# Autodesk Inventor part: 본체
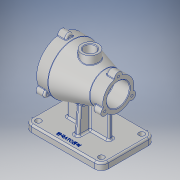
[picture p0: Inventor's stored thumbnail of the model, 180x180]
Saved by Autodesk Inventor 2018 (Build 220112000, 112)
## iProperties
Created: 2020-03
Part Number: 본체
Material: 알루미늄 6061
Document SubType Name: Modeling
Designer: USER
Density: 2.7 g/cm^3
Appearance: 알루미늄 - 평지
Mass: 1007.92 g
Surface Area: 869.539 cm^2
Volume: 373.303 cm^3
Author: USER
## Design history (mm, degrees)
sketch "스케치1"
  geometry: L1 (0, 0)-(100, 0); L2 (100, 0)-(100, 27.5); L3 (100, 27.5)-(77, 27.5); L4 (77, 27.5)-(20, 44); L5 (20, 44)-(0, 44); L6 (0, 44)-(0, 0); L7 (0, 0)-(107.225, 0)
  constraints: 14 end point, 3 perpendicular, 2 horizontal, 1 parallel
  dimensions: "d0" = 20 distance from line of L4.end L6; "d1" = 55 diameter of L3 L7; "d2" = 100 distance between parallel lines of L2 L6; "d3" = 77 distance from line of L3.end L6; "d4" = 88 diameter of L5 L7
revolve "회전1" sketch "스케치1" stored, may be unused: angle "d5" = 90 deg
sketch "스케치2"
  geometry: L1 (0, 0)-(23, 0); L2 (23, 0)-(23, 36); L3 (23, 36)-(0, 36); L4 (0, 36)-(0, 0); L5 (23, 0)-(70, 0); L6 (70, 0)-(70, 26); L7 (70, 26)-(23, 26); L8 (23, 26)-(23, 0); L9 (70, 0)-(100, 0); L10 (100, 0)-(100, 20); L11 (100, 20)-(70, 20); L12 (70, 20)-(70, 0); L13 (100, -27.5)-(100, 27.5) reference; L14 (0, 0)-(130.943, 0)
  constraints: 26 end point, 6 parallel, 4 horizontal, 3 perpendicular, 1 midpoint
  dimensions: "d6" = 40 diameter of L11 L14; "d7" = 52 diameter of L7 L14; "d8" = 72 diameter of L3 L14; "d9" = 23 distance between parallel lines of L2 L4; "d10" = 47 distance between parallel lines of L6 L2
revolve "회전2" sketch "스케치2" stored, may be unused: angle "d11" = 90 deg
node "작업 평면1"
sketch "스케치3"
  geometry: C1 r 15 at (-50, 0); 1 further point
  constraints: 1 centre point, 1 horizontal alignment
  dimensions: "d13" = 30 diameter of C1; "d14" = 50 distance of point (0, 0) C1.centre
extrude "돌출1" join sketch "스케치3" stored distance "d15" = 10; taper "d16" = 0 deg
sketch "스케치4"
  geometry: C1 r 15 at (0, 0) reference; C2 r 10 at (0, 0); 1 further point
  constraints: 1 centre point, 1 coincident
  dimensions: "d17" = 20 diameter of C2
extrude "돌출2" cut sketch "스케치4" distance "d18" = 25.75; taper "d19" = 0 deg
node "작업 평면2"
sketch "스케치6"
  geometry: L1 (0, 44)-(0, -44) reference; L2 (-100, 27.5)-(-100, -27.5) reference; L3 (17.5, -47.5)-(-117.5, -47.5); L4 (-117.5, -47.5)-(-117.5, 47.5); L5 (-117.5, 47.5)-(17.5, 47.5); L6 (17.5, 47.5)-(17.5, -47.5); L7 (0, 0)-(-100, 0); L8 (-50, 0)-(-50, -25.303)
  constraints: 12 end point, 2 midpoint, 2 parallel, 1 horizontal, 1 perpendicular, 1 vertical, 1 other
  dimensions: "d21" = 135 distance between parallel lines of L4 L6; "d22" = 95 distance between parallel lines of L5 L3; "d23" = 47.5 distance from line of L7.start L3
extrude "돌출3" join sketch "스케치6" distance "d24" = 12; taper "d25" = 0 deg
fillet "모깎기1" dims "d26" = 12
sketch "스케치7"
  geometry: L1 (13, 4)-(87, 4); L2 (87, 4)-(87, -4); L3 (87, -4)-(13, -4); L4 (13, -4)-(13, 4); L5 (117.5, 35.5)-(117.5, -35.5) reference; L6 (-17.5, -35.5)-(-17.5, 35.5) reference; L7 (-17.5, 0)-(117.5, 0); L8 (50, 0)-(50, 35.5); 1 further point
  constraints: 12 end point, 3 midpoint, 2 parallel, 1 horizontal, 1 perpendicular, 1 vertical, 1 other
  dimensions: "d27" = 74 distance between parallel lines of L2 L4; "d28" = 8 distance between parallel lines of L3 L1; "d29" = 4 distance from line of point (0, 0) L1
extrude "돌출4" join sketch "스케치7" stored distance "d30" = 12; taper "d31" = 0 deg
node "작업 평면3"
sketch "스케치8"
  geometry: L1 (39.5, 12)-(39.5, 43.182) reference; L2 (31.5, 12)-(39.5, 12) reference; L3 (31.5, 12)-(31.5, 43.182) reference; L4 (31.5, 12)-(39.5, 12) reference; L5 (10.5, 12)-(31.5, 12); L6 (71, 12)-(0, 12) reference; L7 (10.5, 12)-(14.999, 63.425); L8 (14.999, 63.425)-(31.5, 53.896); L9 (31.5, 53.896)-(31.5, 12); L10 (-12, 12)-(0, 12) reference; L11 (35.5, 43)-(35.5, 12); C1 r 36 at (35.5, 87) reference; C2 r 36 at (35.5, 87) reference; C3 r 44 at (35.5, 87) reference; A1 r 44 centre (35.5, 87) between (31.5, 43.182) and (39.5, 43.182) reference; A2 r 44 centre (35.5, 87) between (31.5, 43.182) and (39.5, 43.182) reference; 1 further point
  constraints: 10 end point, 2 point on circle, 1 midpoint, 1 point on line, 1 vertical
  dimensions: "d35" = 95 deg angle of L10 L7; "d91" = 25 distance from line of L11 L5.start
extrude "돌출5" join sketch "스케치8" stored distance "d36" = 8; taper "d37" = 0 deg
sketch "스케치9"
  geometry: L1 (0, 0)-(0, 72.213); C1 r 7 at (0, 44); A1 r 44 centre (0, 0) between (-4, -43.818) and (4, -43.818) reference; A2 r 44 centre (0, 0) between (4, -43.818) and (-4, -43.818) reference; 1 further point
  constraints: 2 end point, 1 centre point, 1 point on circle, 1 point on line, 1 vertical
  dimensions: "d38" = 14 diameter of C1
extrude "돌출6" join sketch "스케치9" distance "d39" = 15; taper "d40" = 0 deg
sketch "스케치10"
  geometry: A1 r 44 centre (0, -44) between (6.978, -0.557) and (-6.978, -0.557) reference; 2 further points
  constraints: 1 point on circle
hole "구멍1" sketch "스케치10" at (0, 0) diameter "d41" = 4.134; stored, may be unused: countersink angle "d45" = 90 deg, drill point angle "d47" = 118 deg; dims "d42" = 9, "d43" = 4, "d44" = 2, "d46" = 11
sketch "스케치11"
  geometry: L1 (0, 0)-(0, 40.117); C1 r 20 at (0, 0) reference; C2 r 7 at (0, 27.5); A1 r 27.5 centre (0, 0) between (4, -27.208) and (-4, -27.208) reference; A2 r 27.5 centre (0, 0) between (4, -27.208) and (-4, -27.208) reference; 1 further point
  constraints: 2 end point, 1 centre point, 1 point on circle, 1 point on line, 1 vertical
  dimensions: "d51" = 14 diameter of C2
extrude "돌출7" join sketch "스케치11" distance "d52" = 15; taper "d53" = 0 deg
sketch "스케치12"
  geometry: A1 r 7 centre (0, 0) between (6.943, -0.891) and (-6.943, -0.891) reference; 1 further point
hole "구멍2" sketch "스케치12" at (0, 0) diameter "d54" = 4.134; stored, may be unused: countersink angle "d58" = 90 deg, drill point angle "d60" = 118 deg; dims "d55" = 9, "d56" = 4, "d57" = 2, "d59" = 11
sketch "스케치13"
  geometry: L1 (-5.5, 47.5)-(105.5, 47.5) reference; L2 (117.5, 35.5)-(117.5, -35.5) reference; L3 (105.5, -47.5)-(-5.5, -47.5) reference; L4 (-17.5, -35.5)-(-17.5, 35.5) reference; C1 r 5 at (-5.5, 35.5); C2 r 5 at (105.5, 35.5); C3 r 5 at (105.5, -35.5); C4 r 5 at (-5.5, -35.5); A1 r 12 centre (-5.5, 35.5) between (-5.5, 47.5) and (-17.5, 35.5) reference; A2 r 12 centre (105.5, -35.5) between (105.5, -47.5) and (117.5, -35.5) reference; A3 r 12 centre (-5.5, 35.5) between (-5.5, 47.5) and (-17.5, 35.5) reference; A4 r 12 centre (105.5, 35.5) between (117.5, 35.5) and (105.5, 47.5) reference; A5 r 12 centre (105.5, -35.5) between (105.5, -47.5) and (117.5, -35.5) reference; A6 r 12 centre (-5.5, -35.5) between (-17.5, -35.5) and (-5.5, -47.5) reference; 1 further point
  constraints: 4 centre point, 4 coincident
  dimensions: "d64" = 10 diameter of C1; "d65" = 10 diameter of C2; "d66" = 10 diameter of C3; "d67" = 10 diameter of C4
extrude "돌출8" cut sketch "스케치13" distance "d68" = 15; taper "d69" = 0 deg
fillet "모깎기2" dims "d70" = 3
fillet "모깎기4" dims "d72" = 3
fillet "모깎기5" dims "d73" = 3
fillet "모깎기6" dims "d74" = 3
fillet "모깎기7" dims "d75" = 1
fillet "모깎기8" dims "d76" = 3
chamfer "모따기1" distance "d77" = 1; stored, may be unused: second distance "d78" = 2, angle "d79" = 45 deg
chamfer "모따기2" distance "d80" = 1; stored, may be unused: second distance "d81" = 2, angle "d82" = 45 deg
fillet "모깎기9" dims "d83" = 3
node "작업 평면4"
sketch "스케치15"
  geometry: L1 (-5.5, -47.5)-(105.5, -47.5) reference; L2 (117.5, -35.5)-(117.5, 35.5) reference; 2 further points
  constraints: 1 other
  dimensions: "d85" = 10 distance from line of L1 point (50, -37.5); "d86" = 67.5 distance from line of L2 point (50, -37.5)
feature "엠보싱1" sketch "스케치15" dims "d6" = 40, "d7" = 52, "d8" = 72, "d9" = 23, "d10" = 47, "d87" = 0.5, "d88" = 0
fillet "모깎기10" dims "d89" = 1
fillet "모깎기11" dims "d92" = 3
node "솔리드1"
mirror "미러1"
pattern_circular "원형 패턴1" dims angle "d49" = 360 deg
pattern_circular "원형 패턴2" dims angle "d62" = 360 deg
node "투영된 루프1"
node "투영된 루프2"
node "투영된 루프3"
node "투영된 루프4"
other parameters: "d12" = 45, "d20" = -87, "d32" = -67.5
